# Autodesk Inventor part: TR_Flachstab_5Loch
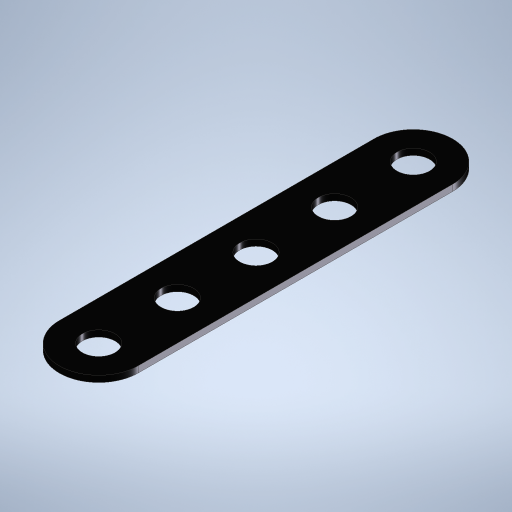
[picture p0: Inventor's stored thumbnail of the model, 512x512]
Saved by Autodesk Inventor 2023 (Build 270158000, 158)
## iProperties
Created: 2023-11
Part Number: TR_Flachstab_5Loch
Material: Edelstahl
Document SubType Name: Modeling
Designer: Admin
Density: 8 g/cm^3
Appearance: Halbpoliert
Author: Admin
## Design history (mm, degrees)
sketch "Skizze1"
  geometry: L1 (0, 20)-(0, -20); L2 (-5, 20)-(-5, -20); L3 (5, -20)-(5, 20); A1 r 5 centre (0, 20) between (5, 20) and (-5, 20); A2 r 5 centre (0, -20) between (-5, -20) and (5, -20); 3 further points
  constraints: 8 end point, 4 point on circle, 4 tangent, 2 centre point, 2 midpoint, 1 horizontal alignment, 1 parallel, 1 vertical, 1 vertical alignment
  dimensions: "d0" = 40 distance of L1.start L1.end (computed from Loch, Einheitsmaß); "d1" = 5 radius of A1 (= 0.5 x Einheitsmaß)
extrude "Extrusion1" new body sketch "Skizze1" distance "d5" = 0.8 (= Dicke); taper "d6" = 0 deg
sketch "Skizze2"
  geometry: C1 r 2.075 at (0, 20); A1 r 5 centre (0, 20) between (5, 20) and (-5, 20) reference; 1 further point
  constraints: 1 centre point, 1 coincident
  dimensions: "d7" = 4.15 diameter of C1 (= 2 x Radius)
extrude "Extrusion2" cut sketch "Skizze2" stored distance "d8" = 10; taper "d9" = 0 deg
pattern_linear "Rechteckige Anordnung1" dims "d12" = 10 (= Einheitsmaß)
node "Volumenkörper1"
other parameters: "Einheitsmaß" = 10 [user parameter; used in 3 equation terms], "Radius" = 2.075 [user parameter; used in 1 equation term], "Fasen" = 0.5 [user parameter], "Dicke" = 0.8 [user parameter; used in 1 equation term]
